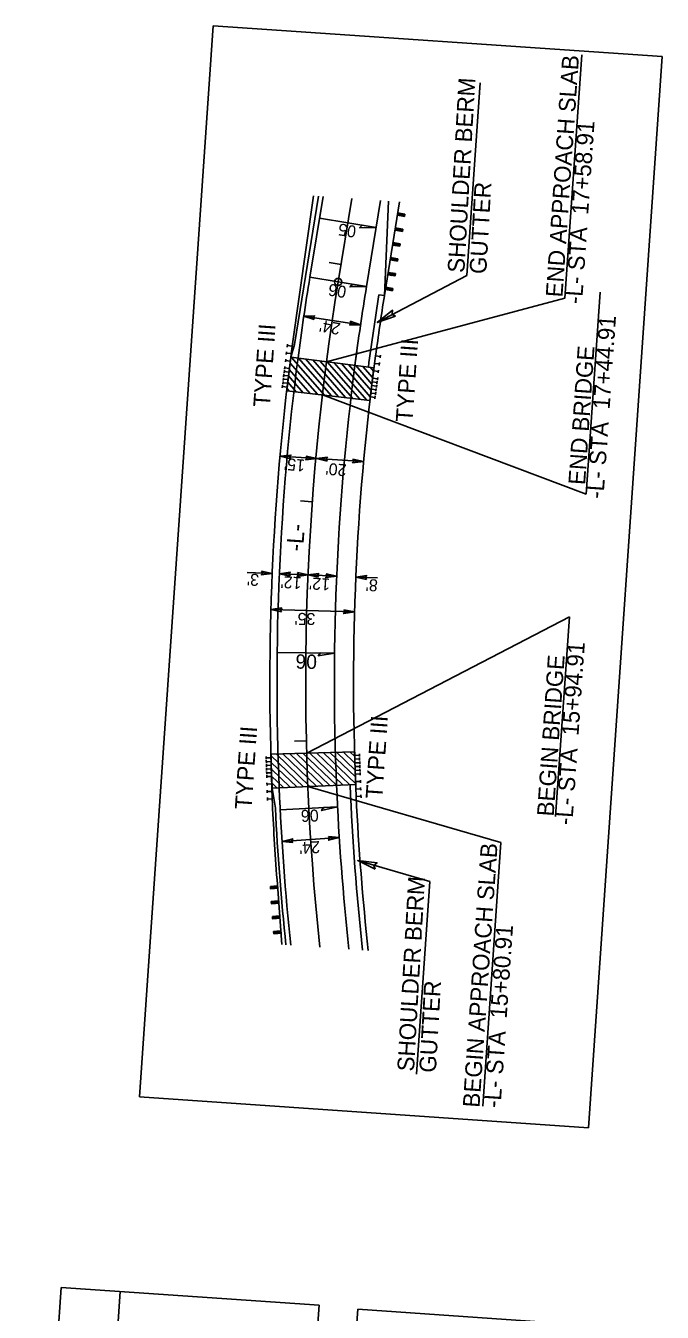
# Model space of a CAD drawing. Extents: x 2599146 to 2600072, y 728518 to 730269.
# Drawn here: x 2599806 to 2600072, y 729444 to 729982 of the extents above; entities that cross this region are included whole.
import ezdxf

# ---------------------------------------------------------------- set-up
doc = ezdxf.new("R2010")
doc.units = 0
for name, color, linetype in [('Default', 7, 'Continuous'), ('Old_Level_23', 7, 'Continuous'), ('Prop Conc Shoulder Berm Gutter', 7, 'Continuous'), ('Prop Dimension', 7, 'Continuous'), ('Prop Dimension Text', 7, 'Continuous'), ('Prop EOT', 7, 'Continuous'), ('Prop Guardrail', 7, 'Continuous'), ('Prop Guardrail Anchor Unit CELL', 7, 'Continuous'), ('Prop Horizontal Alignment', 7, 'Continuous'), ('Prop Horizontal Alignment Station Label', 7, 'Continuous'), ('Prop Horizontal Alignment Tick Small', 7, 'Continuous'), ('Prop Lane Lines', 7, 'Continuous'), ('Prop Roadway Bridge', 7, 'Continuous'), ('Prop Structure Anchor Unit CELL', 7, 'Continuous'), ('Prop Superelevation Label', 7, 'Continuous'), ('Prop Terminator CELL', 7, 'Continuous')]:
    doc.layers.add(name, color=color, linetype=linetype)

msp = doc.modelspace()

# ---------------------------------------------------------------- linework, layer by layer
at = {"layer": 'Default'}
for p, q in [((2599853.24, 729534.06), (2599884.08, 729981.85)), ((2599884.08, 729981.85), (2600071.79, 729968.92)), ((2600071.79, 729968.92), (2600040.95, 729521.13)), ((2599853.24, 729534.06), (2600040.95, 729521.13))]:
    msp.add_line(p, q, dxfattribs=at)
at = {"layer": 'Old_Level_23'}
for p, q in [((2599805.64, 729239.58), (2599820.44, 729454.39)), ((2599820.44, 729454.39), (2599928.32, 729446.96)), ((2599830.37, 729237.87), (2599845.17, 729452.69)), ((2599913.52, 729232.15), (2599928.32, 729446.96)), ((2599929.66, 729230.3), (2599944.47, 729445.24)), ((2599944.47, 729445.24), (2600044.61, 729438.34))]:
    msp.add_line(p, q, dxfattribs=at)
at = {"layer": 'Prop Conc Shoulder Berm Gutter'}
msp.add_line((2599953.3, 729869.37), (2599955.62, 729869), dxfattribs=at)
for start, end in [(170.87965, 172.59246), (182.39886, 186.2884)]:
    msp.add_arc((2600962.71, 729707.32), 1022.34, start, end, dxfattribs=at)
at = {"layer": 'Prop Dimension'}
for p, q in [((2600031.1, 729868.01), (2600038.1, 729969.73)), ((2599995.61, 729957.98), (2599990.06, 729877.46)), ((2599952.64, 729857.78), (2599990.06, 729877.46)), ((2599931.39, 729841.4), (2600031.1, 729868.01)), ((2600040.02, 729786.04), (2600045.84, 729870.47)), ((2599945.65, 729856.86), (2599921.92, 729860.49)), ((2599929.68, 729827.51), (2600040.02, 729786.04)), ((2599911.96, 729801.87), (2599927.3, 729800.9)), ((2599927.2, 729800.91), (2599946.9, 729799.65)), ((2599898.27, 729753.33), (2599908.7, 729752.88)), ((2599911.69, 729752.75), (2599923.68, 729752.23)), ((2599923.58, 729752.23), (2599935.67, 729751.71)), ((2599952.68, 729750.98), (2599943.66, 729751.37)), ((2599908.15, 729737.79), (2599943.14, 729736.78)), ((2599923.13, 729677.78), (2600032.95, 729734.68)), ((2600032.95, 729734.68), (2600027.2, 729651.19)), ((2599923.62, 729663.79), (2600004.29, 729640.33)), ((2599936.76, 729642.41), (2599912.82, 729640.82)), ((2600004.29, 729640.33), (2599996.71, 729530.2)), ((2599944.48, 729632.83), (2599974.55, 729624.09)), ((2599974.55, 729624.09), (2599969.01, 729543.57))]:
    msp.add_line(p, q, dxfattribs=at)
at = {"layer": 'Prop EOT'}
for p, q in [((2599918, 729848.56), (2599928.09, 729910.58)), ((2599924.43, 729876.67), (2599929.94, 729910.46)), ((2599948.12, 729872.81), (2599953.99, 729908.8)), ((2599955.61, 729869), (2599957.27, 729908.57)), ((2599918, 729848.56), (2599916.52, 729843.34)), ((2599910.02, 729654.76), (2599908.64, 729663.16))]:
    msp.add_line(p, q, dxfattribs=at)
for radius, start, end in [(1052, 170.73628, 172.59246), (1028, 170.73628, 172.59246), (1052, 182.39886, 185.99676), (1028, 182.39886, 186.23143), (1054, 182.85838, 185.9777)]:
    msp.add_arc((2600962.71, 729707.32), radius, start, end, dxfattribs=at)
at = {"layer": 'Prop Guardrail'}
for p, q in [((2599925.99, 729910.73), (2599916.98, 729847.86)), ((2599956.02, 729871.52), (2599956.33, 729873.42))]:
    msp.add_line(p, q, dxfattribs=at)
for centre, radius, start, end in [((2600967.68, 729708.63), 1024.69, 170.996, 172.42023), ((2600959.13, 729704.54), 1051.44, 182.5033, 184.34879), ((2600960.26, 729707.15), 1017.56, 182.67771, 186.31768)]:
    msp.add_arc(centre, radius, start, end, dxfattribs=at)
at = {"layer": 'Prop Guardrail Anchor Unit CELL'}
for p, q in [((2599955.62, 729869), (2599961.98, 729908.24)), ((2599961.06, 729902.61), (2599962.71, 729903.36)), ((2599961.22, 729903.6), (2599964.19, 729903.12)), ((2599962.55, 729902.37), (2599961.22, 729903.6)), ((2599962.55, 729902.37), (2599962.71, 729903.36)), ((2599962.71, 729903.36), (2599964.03, 729902.13)), ((2599961.06, 729902.61), (2599964.03, 729902.13)), ((2599964.19, 729903.12), (2599962.55, 729902.37)), ((2599964.03, 729902.13), (2599964.19, 729903.12)), ((2599960.06, 729896.39), (2599961.77, 729897.12)), ((2599960.06, 729896.39), (2599963.15, 729895.89)), ((2599960.22, 729897.38), (2599963.31, 729896.87)), ((2599961.61, 729896.14), (2599960.22, 729897.38)), ((2599961.61, 729896.14), (2599961.77, 729897.12)), ((2599963.31, 729896.87), (2599961.61, 729896.14)), ((2599961.77, 729897.12), (2599963.15, 729895.89)), ((2599963.15, 729895.89), (2599963.31, 729896.87)), ((2599959.05, 729890.17), (2599959.21, 729891.16)), ((2599959.05, 729890.17), (2599960.71, 729890.91)), ((2599959.05, 729890.17), (2599962.05, 729889.68)), ((2599959.21, 729891.16), (2599962.21, 729890.67)), ((2599960.55, 729889.93), (2599959.21, 729891.16)), ((2599960.55, 729889.93), (2599960.71, 729890.91)), ((2599962.21, 729890.67), (2599960.55, 729889.93)), ((2599960.71, 729890.91), (2599962.05, 729889.68)), ((2599962.05, 729889.68), (2599962.21, 729890.67)), ((2599958.04, 729883.95), (2599959.71, 729884.69)), ((2599958.04, 729883.95), (2599961.05, 729883.46)), ((2599958.2, 729884.94), (2599961.21, 729884.45)), ((2599959.55, 729883.71), (2599958.2, 729884.94)), ((2599959.55, 729883.71), (2599959.71, 729884.69)), ((2599961.21, 729884.45), (2599959.55, 729883.71)), ((2599959.71, 729884.69), (2599961.05, 729883.46)), ((2599961.05, 729883.46), (2599961.21, 729884.45)), ((2599957.03, 729877.73), (2599958.7, 729878.47)), ((2599957.03, 729877.73), (2599960.05, 729877.24)), ((2599957.19, 729878.72), (2599960.21, 729878.23)), ((2599958.54, 729877.49), (2599957.19, 729878.72)), ((2599958.54, 729877.49), (2599958.7, 729878.47)), ((2599960.21, 729878.23), (2599958.54, 729877.49)), ((2599958.7, 729878.47), (2599960.05, 729877.24)), ((2599960.05, 729877.24), (2599960.21, 729878.23)), ((2599956.03, 729871.51), (2599956.19, 729872.5)), ((2599957.67, 729872.26), (2599956.03, 729871.51)), ((2599956.03, 729871.51), (2599958.99, 729871.03)), ((2599956.19, 729872.5), (2599959.15, 729872.02)), ((2599956.19, 729872.5), (2599957.67, 729872.26)), ((2599957.51, 729871.27), (2599956.19, 729872.5)), ((2599957.51, 729871.27), (2599957.67, 729872.26)), ((2599959.15, 729872.02), (2599957.51, 729871.27)), ((2599957.67, 729872.26), (2599958.99, 729871.03)), ((2599958.99, 729871.03), (2599959.15, 729872.02)), ((2599910.72, 729624.81), (2599912.74, 729597.67)), ((2599910.91, 729622.28), (2599907.92, 729622.05)), ((2599909.49, 729621.17), (2599907.92, 729622.05)), ((2599907.92, 729622.05), (2599907.99, 729621.05)), ((2599907.99, 729621.05), (2599909.41, 729622.16)), ((2599910.98, 729621.28), (2599907.99, 729621.05)), ((2599909.41, 729622.16), (2599909.49, 729621.17)), ((2599909.41, 729622.16), (2599910.98, 729621.28)), ((2599909.49, 729621.17), (2599910.91, 729622.28)), ((2599910.98, 729621.28), (2599909.49, 729621.17)), ((2599910.91, 729622.28), (2599910.98, 729621.28)), ((2599911.38, 729615.99), (2599908.33, 729615.76)), ((2599909.93, 729614.88), (2599908.33, 729615.76)), ((2599908.33, 729615.76), (2599908.41, 729614.77)), ((2599908.41, 729614.77), (2599909.85, 729615.88)), ((2599911.45, 729614.99), (2599908.41, 729614.77)), ((2599909.85, 729615.88), (2599909.93, 729614.88)), ((2599909.85, 729615.88), (2599911.45, 729614.99)), ((2599911.38, 729615.99), (2599909.93, 729614.88)), ((2599911.84, 729609.71), (2599908.81, 729609.48)), ((2599910.4, 729608.6), (2599908.81, 729609.48)), ((2599908.81, 729609.48), (2599908.88, 729608.48)), ((2599908.88, 729608.48), (2599910.32, 729609.59)), ((2599911.92, 729608.71), (2599908.88, 729608.48)), ((2599910.32, 729609.59), (2599910.4, 729608.6)), ((2599910.32, 729609.59), (2599911.92, 729608.71)), ((2599911.84, 729609.71), (2599910.4, 729608.6)), ((2599912.31, 729603.42), (2599909.29, 729603.2)), ((2599910.87, 729602.31), (2599909.29, 729603.2)), ((2599909.29, 729603.2), (2599909.36, 729602.2)), ((2599909.36, 729602.2), (2599910.8, 729603.31)), ((2599912.39, 729602.43), (2599909.36, 729602.2)), ((2599910.8, 729603.31), (2599910.87, 729602.31)), ((2599910.8, 729603.31), (2599912.39, 729602.43)), ((2599912.31, 729603.42), (2599910.87, 729602.31)), ((2599912.31, 729603.42), (2599912.39, 729602.43))]:
    msp.add_line(p, q, dxfattribs=at)
at = {"layer": 'Prop Horizontal Alignment'}
msp.add_line((2599936.28, 729874.74), (2599941.97, 729909.63), dxfattribs=at)
msp.add_arc((2600962.71, 729707.32), 1040, 170.73628, 186.11272, dxfattribs=at)
at = {"layer": 'Prop Horizontal Alignment Station Label'}
msp.add_circle((2599936.28, 729874.74), 1.5, dxfattribs=at)
at = {"layer": 'Prop Horizontal Alignment Tick Small'}
for p, q in [((2599937.47, 729882.04), (2599932.53, 729882.85)), ((2599925.46, 729782.8), (2599920.47, 729783.17)), ((2599923, 729682.87), (2599918, 729682.75))]:
    msp.add_line(p, q, dxfattribs=at)
at = {"layer": 'Prop Lane Lines'}
for radius, start in [(1028, 172.27238), (1052, 172.59246)]:
    msp.add_arc((2600962.71, 729707.32), radius, start, 182.39886, dxfattribs=at)
at = {"layer": 'Prop Roadway Bridge'}
for p, q in [((2599927.59, 729827.75), (2599916.2, 729840.84)), ((2599951.23, 729838.83), (2599916.52, 729843.34)), ((2599930.54, 729827.41), (2599916.69, 729843.32)), ((2599933.5, 729827.07), (2599919.68, 729842.93)), ((2599936.45, 729826.72), (2599922.67, 729842.54)), ((2599939.4, 729826.38), (2599925.66, 729842.15)), ((2599942.35, 729826.04), (2599928.65, 729841.76)), ((2599945.3, 729825.69), (2599931.64, 729841.37)), ((2599948.25, 729825.35), (2599934.63, 729840.98)), ((2599949.72, 729826.71), (2599937.62, 729840.59)), ((2599950.04, 729829.39), (2599940.62, 729840.21)), ((2599950.37, 729832.06), (2599943.61, 729839.82)), ((2599950.7, 729834.72), (2599946.6, 729839.43)), ((2599951.04, 729837.37), (2599949.59, 729839.04)), ((2599921.69, 729828.44), (2599915.53, 729835.51)), ((2599924.64, 729828.1), (2599915.86, 729838.18)), ((2599949.55, 729825.2), (2599914.78, 729829.24)), ((2599915.79, 729829.13), (2599914.89, 729830.16)), ((2599918.74, 729828.78), (2599915.21, 729832.84)), ((2599908.14, 729677.36), (2599943.12, 729678.35)), ((2599924.49, 729663.83), (2599910.34, 729677.42)), ((2599927.25, 729663.94), (2599913.14, 729677.5)), ((2599930.02, 729664.06), (2599915.94, 729677.58)), ((2599932.79, 729664.18), (2599918.75, 729677.66)), ((2599935.55, 729664.29), (2599921.55, 729677.74)), ((2599938.32, 729664.41), (2599924.36, 729677.82)), ((2599941.09, 729664.52), (2599927.16, 729677.9)), ((2599943.6, 729664.89), (2599929.97, 729677.98)), ((2599943.48, 729667.77), (2599932.77, 729678.06)), ((2599943.37, 729670.65), (2599935.57, 729678.14)), ((2599943.27, 729673.52), (2599938.38, 729678.22)), ((2599943.18, 729676.38), (2599941.18, 729678.3)), ((2599921.72, 729663.71), (2599908.16, 729676.74)), ((2599918.95, 729663.6), (2599908.24, 729673.88)), ((2599916.19, 729663.48), (2599908.34, 729671.02)), ((2599913.42, 729663.36), (2599908.44, 729668.15)), ((2599910.65, 729663.25), (2599908.55, 729665.27)), ((2599943.61, 729664.63), (2599908.64, 729663.16))]:
    msp.add_line(p, q, dxfattribs=at)
for radius in [1055, 1020]:
    msp.add_arc((2600962.71, 729707.32), radius, 172.59247, 182.39886, dxfattribs=at)
at = {"layer": 'Prop Structure Anchor Unit CELL'}
for p, q in [((2599914.56, 729844.43), (2599914.7, 729845.56)), ((2599916.62, 729844.76), (2599914.63, 729845)), ((2599914.78, 729829.24), (2599916.98, 729847.86)), ((2599914.93, 729847.53), (2599915.07, 729848.67)), ((2599916.98, 729847.86), (2599915, 729848.1)), ((2599953.86, 729842.97), (2599954, 729844.11)), ((2599913.83, 729838.22), (2599913.96, 729839.36)), ((2599915.88, 729838.55), (2599913.9, 729838.79)), ((2599914.2, 729841.32), (2599914.33, 729842.46)), ((2599916.25, 729841.66), (2599914.26, 729841.89)), ((2599949.55, 729825.2), (2599951.95, 729843.79)), ((2599951.55, 729840.7), (2599953.53, 729840.44)), ((2599951.95, 729843.79), (2599953.93, 729843.54)), ((2599953.46, 729839.87), (2599953.6, 729841.01)), ((2599913.28, 729833.56), (2599913.41, 729834.7)), ((2599915.33, 729833.9), (2599913.35, 729834.13)), ((2599913.46, 729835.12), (2599913.6, 729836.25)), ((2599915.52, 729835.45), (2599913.53, 729835.69)), ((2599913.65, 729836.67), (2599913.78, 729837.81)), ((2599915.7, 729837), (2599913.71, 729837.24)), ((2599950.75, 729834.5), (2599952.73, 729834.24)), ((2599951.15, 729837.6), (2599953.13, 729837.34)), ((2599952.46, 729832.12), (2599952.6, 729833.26)), ((2599952.66, 729833.67), (2599952.8, 729834.81)), ((2599953.06, 729836.77), (2599953.2, 729837.91)), ((2599912.91, 729830.46), (2599913.05, 729831.6)), ((2599914.96, 729830.8), (2599912.98, 729831.03)), ((2599913.1, 729832.01), (2599913.23, 729833.15)), ((2599915.15, 729832.35), (2599913.16, 729832.58)), ((2599949.95, 729828.3), (2599951.93, 729828.04)), ((2599950.15, 729829.85), (2599952.13, 729829.59)), ((2599950.35, 729831.4), (2599952.33, 729831.14)), ((2599950.55, 729832.95), (2599952.53, 729832.69)), ((2599951.86, 729827.47), (2599952, 729828.61)), ((2599952.06, 729829.02), (2599952.2, 729830.16)), ((2599952.26, 729830.57), (2599952.4, 729831.71)), ((2599949.75, 729826.75), (2599951.73, 729826.49)), ((2599951.66, 729825.92), (2599951.8, 729827.06)), ((2599908.14, 729677.36), (2599908.69, 729658.62)), ((2599943.12, 729678.35), (2599943.81, 729659.61)), ((2599945.16, 729677.44), (2599945.2, 729676.29)), ((2599906.17, 729676.31), (2599906.2, 729675.16)), ((2599908.18, 729675.8), (2599906.19, 729675.74)), ((2599906.21, 729674.75), (2599906.25, 729673.6)), ((2599908.23, 729674.23), (2599906.23, 729674.17)), ((2599906.26, 729673.18), (2599906.3, 729672.04)), ((2599908.28, 729672.67), (2599906.28, 729672.61)), ((2599943.18, 729676.79), (2599945.18, 729676.86)), ((2599943.24, 729675.23), (2599945.24, 729675.3)), ((2599943.3, 729673.67), (2599945.29, 729673.74)), ((2599943.35, 729672.11), (2599945.35, 729672.18)), ((2599945.22, 729675.87), (2599945.26, 729674.73)), ((2599945.27, 729674.31), (2599945.32, 729673.17)), ((2599945.33, 729672.75), (2599945.37, 729671.61)), ((2599906.31, 729671.62), (2599906.34, 729670.48)), ((2599908.32, 729671.11), (2599906.32, 729671.05)), ((2599906.35, 729670.06), (2599906.39, 729668.92)), ((2599908.37, 729669.55), (2599906.37, 729669.49)), ((2599906.4, 729668.5), (2599906.43, 729667.35)), ((2599908.42, 729667.99), (2599906.42, 729667.93)), ((2599943.41, 729670.54), (2599945.41, 729670.62)), ((2599943.47, 729668.98), (2599945.47, 729669.06)), ((2599945.39, 729671.19), (2599945.43, 729670.04)), ((2599945.45, 729669.63), (2599945.49, 729668.48)), ((2599906.49, 729665.38), (2599906.53, 729664.23)), ((2599908.51, 729664.86), (2599906.51, 729664.8)), ((2599906.59, 729662.25), (2599906.62, 729661.11)), ((2599908.6, 729661.74), (2599906.6, 729661.68)), ((2599943.58, 729665.86), (2599945.58, 729665.93)), ((2599943.7, 729662.74), (2599945.7, 729662.81)), ((2599945.56, 729666.51), (2599945.6, 729665.36)), ((2599945.67, 729663.38), (2599945.72, 729662.24)), ((2599906.68, 729659.13), (2599906.71, 729657.98)), ((2599908.69, 729658.62), (2599906.69, 729658.56)), ((2599943.81, 729659.61), (2599945.81, 729659.69)), ((2599945.79, 729660.26), (2599945.83, 729659.11))]:
    msp.add_line(p, q, dxfattribs=at)
at = {"layer": 'Prop Superelevation Label'}
for p, q in [((2599952.14, 729897.48), (2599928.46, 729901.35)), ((2599948.12, 729872.81), (2599924.43, 729876.67)), ((2599910.79, 729719.82), (2599934.79, 729719.54)), ((2599912.06, 729654.06), (2599936.03, 729655.28))]:
    msp.add_line(p, q, dxfattribs=at)
at = {"layer": 'Prop Terminator CELL'}
for points in [[(2599952.14, 729897.48), (2599945.25, 729897.39), (2599946.3, 729898.44)], [(2599948.1, 729872.81), (2599941.21, 729872.68), (2599942.25, 729873.73)], [(2599926.25, 729859.04), (2599921.92, 729860.49), (2599926.52, 729860.6), (2599925.83, 729859.89)], [(2599960.3, 729860.39), (2599952.64, 729857.78), (2599959, 729862.87), (2599958.79, 729861.13)], [(2599941.32, 729858.31), (2599945.65, 729856.86), (2599941.05, 729856.76), (2599941.74, 729857.46)], [(2599916.4, 729800.81), (2599911.96, 729801.87), (2599916.52, 729802.38), (2599915.9, 729801.62)], [(2599922.86, 729801.96), (2599927.3, 729800.9), (2599922.74, 729800.39), (2599923.36, 729801.15)], [(2599931.64, 729799.85), (2599927.2, 729800.91), (2599931.76, 729801.42), (2599931.14, 729800.65)], [(2599942.46, 729800.71), (2599946.9, 729799.65), (2599942.33, 729799.14), (2599942.96, 729799.9)], [(2599904.23, 729753.85), (2599908.7, 729752.88), (2599904.14, 729752.27), (2599904.75, 729753.05)], [(2599916.16, 729751.78), (2599911.69, 729752.75), (2599916.25, 729753.35), (2599915.64, 729752.58)], [(2599919.22, 729753.2), (2599923.68, 729752.23), (2599919.13, 729751.62), (2599919.74, 729752.4)], [(2599928.04, 729751.26), (2599923.58, 729752.23), (2599928.13, 729752.84), (2599927.52, 729752.06)], [(2599931.21, 729752.68), (2599935.67, 729751.71), (2599931.12, 729751.11), (2599931.73, 729751.88)], [(2599948.13, 729750.4), (2599943.66, 729751.37), (2599948.22, 729751.97), (2599947.61, 729751.19)], [(2599912.63, 729736.88), (2599908.15, 729737.79), (2599912.7, 729738.46), (2599912.1, 729737.67)], [(2599938.66, 729737.68), (2599943.14, 729736.78), (2599938.59, 729736.11), (2599939.19, 729736.89)], [(2599934.79, 729719.54), (2599927.97, 729718.48), (2599928.86, 729719.66)], [(2599936.03, 729655.28), (2599929.31, 729653.73), (2599930.11, 729654.98)], [(2599917.36, 729640.35), (2599912.82, 729640.82), (2599917.28, 729641.92), (2599916.76, 729641.08)], [(2599932.22, 729642.89), (2599936.76, 729642.41), (2599932.3, 729641.32), (2599932.82, 729642.15)], [(2599951.72, 729629.22), (2599944.48, 729632.83), (2599952.56, 729631.88), (2599951.18, 729630.82)]]:
    msp.add_lwpolyline(points, close=True, dxfattribs=at)

# ---------------------------------------------------------------- texts
at = {"layer": 'Default'}
for s, p in [('END APPROACH SLAB', (2600030.04, 729868.17)), ('-L- STA  17+58.91', (2600038.23, 729865.35)), ('-L- STA  17+44.91', (2600047.19, 729783.95)), ('END BRIDGE', (2600039.49, 729789.71)), ('-L- STA  15+94.91', (2600034.17, 729647.49)), ('BEGIN BRIDGE', (2600026.37, 729651.14)), ('BEGIN APPROACH SLAB', (2599995.35, 729529.4)), ('-L- STA  15+80.91', (2600004.15, 729529.25))]:
    msp.add_text(s, height=7, rotation=86.0601, dxfattribs=at).set_placement(p)
at = {"layer": 'Prop Dimension Text'}
for s, height, rotation, p in [('SHOULDER BERM', 7, 86.7377, (2599989.01, 729878.41)), ('GUTTER', 7, 86.7377, (2599998.17, 729877.89)), ("24'", 5, 169.6391, (2599937.53, 729857.43)), ("15'", 5, 175.3627, (2599922.58, 729800.42)), ("20'", 5, 175.3627, (2599939.95, 729798.44)), ("3'", 5, 176.5237, (2599903.33, 729752.57)), ("12'", 5, 176.5237, (2599921.08, 729751.28)), ("12'", 5, 176.5237, (2599933.02, 729750.69)), ("8'", 5, 176.5237, (2599952.98, 729750.28)), ("35'", 5, 179.4114, (2599926.78, 729736.3)), ("24'", 5, 183.0943, (2599928.56, 729640.99)), ('SHOULDER BERM', 7, 86.7377, (2599967.96, 729544.52)), ('GUTTER', 7, 86.7377, (2599977.12, 729544))]:
    msp.add_text(s, height=height, rotation=rotation, dxfattribs=at).set_placement(p)
at = {"layer": 'Prop Horizontal Alignment Station Label'}
msp.add_text('-L-', height=7, rotation=86.0601, dxfattribs=at).set_placement((2599921.59, 729761.93))
at = {"layer": 'Prop Structure Anchor Unit CELL'}
for p in [(2599907.74, 729822.21), (2599967.32, 729815.94), (2599900.04, 729654.01), (2599954.72, 729658.43)]:
    msp.add_text('TYPE III', height=7, rotation=86.0601, dxfattribs=at).set_placement(p)
at = {"layer": 'Prop Superelevation Label'}
for s, height, rotation, p in [('05', 5, 171.1283, (2599944.09, 729898.1)), ('06', 5, 171.1283, (2599939.97, 729872.88)), ('06', 6, 179.0851, (2599927.45, 729718.93)), ('06', 5, 182.0765, (2599928.03, 729654.21))]:
    msp.add_text(s, height=height, rotation=rotation, dxfattribs=at).set_placement(p)

doc.saveas('drawing.dxf')
